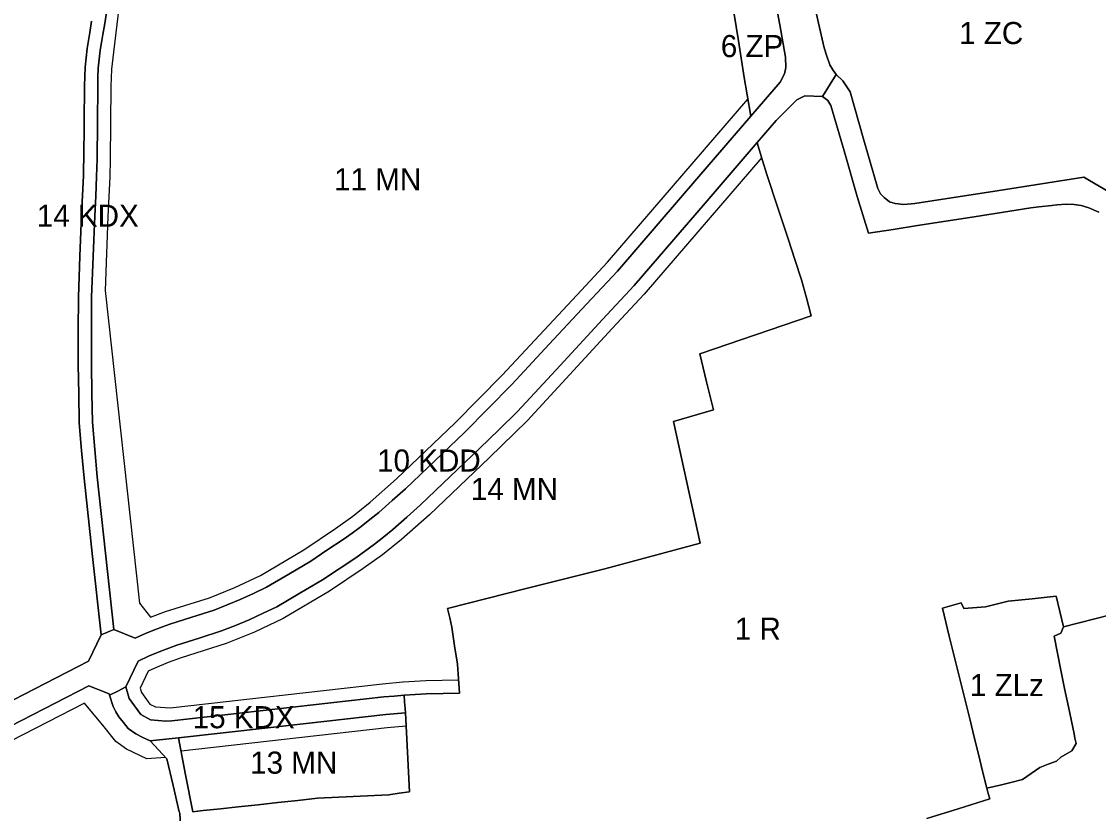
# Model space of a CAD drawing. Extents: x -294445 to -292055, y 21869 to 23693.
# Drawn here: x -293269.7 to -292783, y 22240.3 to 22598.3 of the extents above; entities that cross this region are included whole.
import ezdxf

# ---------------------------------------------------------------- set-up
doc = ezdxf.new("R2010")
doc.units = 0
for name, color, linetype in [('linie_rozgraniczajace', 7, 'Continuous'), ('linie_zabudowy_nieprzekraczalne', 7, 'Continuous'), ('oznaczenia_przeznaczen', 7, 'Continuous')]:
    doc.layers.add(name, color=color, linetype=linetype)

msp = doc.modelspace()

# ---------------------------------------------------------------- linework, layer by layer
at = {"layer": 'linie_rozgraniczajace'}
for points in [[(-293302.714, 22276.673), (-293239.368, 22309.206), (-293233.787, 22321.003), (-293227.916, 22323.482), (-293223.142, 22321.508), (-293218.368, 22319.534), (-293216.059, 22320.643), (-293212.623, 22322.071), (-293209.188, 22323.5), (-293205.936, 22324.686), (-293202.683, 22325.873), (-293192.683, 22329.039), (-293182.683, 22332.205), (-293176.773, 22334.589), (-293170.863, 22336.974), (-293164.904, 22339.78), (-293158.945, 22342.587), (-293148.961, 22348.488), (-293138.978, 22354.39), (-293131.669, 22359.27), (-293124.361, 22364.15), (-293120.317, 22367.055), (-293116.273, 22369.96), (-293112.279, 22373.19), (-293108.285, 22376.421), (-293102.214, 22381.775), (-293096.144, 22387.128), (-293082.827, 22399.85), (-293069.51, 22412.572), (-293058.845, 22423.426), (-293048.18, 22434.28), (-293031.26, 22452.385), (-293014.34, 22470.49), (-293007.373, 22478.002), (-293000.405, 22485.515), (-292963.658, 22528.21), (-292940.132, 22555.546), (-292926.911, 22570.906), (-292924.849, 22574.683), (-292924.231, 22577.549), (-292924.4, 22582.147), (-292927.04, 22596.744), (-292929.68, 22611.34)], [(-292948.75, 22608.3), (-292945.745, 22589.63), (-292943.07, 22572.98), (-292941.74, 22565.09), (-292940.132, 22555.546), (-292963.658, 22528.21), (-293000.405, 22485.515), (-293007.373, 22478.002), (-293014.34, 22470.49), (-293031.26, 22452.385), (-293048.18, 22434.28), (-293058.845, 22423.426), (-293069.51, 22412.572), (-293082.827, 22399.85), (-293096.144, 22387.128), (-293102.214, 22381.775), (-293108.285, 22376.421), (-293112.279, 22373.19), (-293116.273, 22369.96), (-293120.317, 22367.055), (-293124.361, 22364.15), (-293131.669, 22359.27), (-293138.978, 22354.39), (-293148.961, 22348.488), (-293158.945, 22342.587), (-293164.904, 22339.78), (-293170.863, 22336.974), (-293176.773, 22334.589), (-293182.683, 22332.205), (-293192.683, 22329.039), (-293202.683, 22325.873), (-293205.936, 22324.686), (-293209.188, 22323.5)], [(-292911.95, 22608.56), (-292909.465, 22597.52), (-292906.98, 22586.48), (-292905.695, 22582.565), (-292904.41, 22578.65), (-292902.992, 22576.501), (-292901.574, 22574.353), (-292907.675, 22564.371), (-292915.782, 22564.716), (-292919.3, 22562.86), (-292928.711, 22553.485), (-292937.25, 22543.564), (-292960.769, 22516.238), (-292992.826, 22478.991), (-293007.132, 22463.557), (-293026.336, 22442.779), (-293045.54, 22422), (-293054.052, 22413.69), (-293062.563, 22405.379), (-293075.972, 22392.57), (-293089.38, 22379.76)], [(-292768.799, 22515.737), (-292789.634, 22527.91), (-292827.817, 22521.943), (-292866.001, 22515.976), (-292871.033, 22515.575), (-292874.885, 22515.97), (-292877.503, 22516.81), (-292879.91, 22518.674), (-292881.568, 22520.42), (-292882.733, 22522.768), (-292886.349, 22535.383), (-292889, 22544.63), (-292895.267, 22566.493), (-292898.581, 22571.486), (-292901.574, 22574.353), (-292902.992, 22576.501), (-292904.41, 22578.65), (-292905.695, 22582.565), (-292906.98, 22586.48), (-292909.465, 22597.52), (-292911.95, 22608.56)], [(-293231.274, 22602.401), (-293232.126, 22597.42), (-293232.979, 22592.438), (-293233.538, 22588.876), (-293234.098, 22585.314), (-293234.558, 22581.267), (-293235.019, 22577.221), (-293235.151, 22573.148), (-293235.283, 22569.075), (-293235.433, 22552.559), (-293235.583, 22536.042), (-293235.666, 22532.166), (-293235.75, 22528.29), (-293236.185, 22519.39), (-293236.62, 22510.49), (-293237.325, 22492.06), (-293238.03, 22473.63), (-293238.09, 22458.43), (-293238.15, 22443.23), (-293237.885, 22430.2), (-293237.62, 22417.17), (-293236.555, 22404.835), (-293235.49, 22392.5), (-293231.703, 22357.991), (-293227.916, 22323.482), (-293233.787, 22321.003), (-293237.624, 22356.459), (-293241.462, 22391.915), (-293242.538, 22404.383), (-293243.615, 22416.851), (-293243.882, 22430.016), (-293244.15, 22443.181), (-293244.09, 22458.469), (-293244.03, 22473.757), (-293243.322, 22492.254), (-293242.614, 22510.751), (-293242.181, 22519.626), (-293241.747, 22528.501), (-293241.665, 22532.275), (-293241.584, 22536.049), (-293241.432, 22552.659), (-293241.28, 22569.27), (-293241.144, 22573.464), (-293241.008, 22577.658), (-293240.526, 22581.888), (-293240.045, 22586.119), (-293239.472, 22589.764), (-293238.9, 22593.41), (-293238.035, 22598.462)], [(-293238.15, 22443.23), (-293238.09, 22458.43), (-293238.03, 22473.63), (-293237.325, 22492.06), (-293236.62, 22510.49), (-293236.185, 22519.39), (-293235.75, 22528.29), (-293235.666, 22532.166), (-293235.583, 22536.042), (-293235.433, 22552.559), (-293235.283, 22569.075), (-293235.151, 22573.148), (-293235.019, 22577.221), (-293234.558, 22581.267), (-293234.098, 22585.314), (-293233.538, 22588.876), (-293232.979, 22592.438), (-293232.126, 22597.42), (-293231.274, 22602.401)], [(-293238.035, 22598.462), (-293238.9, 22593.41), (-293239.472, 22589.764), (-293240.045, 22586.119), (-293240.526, 22581.888), (-293241.008, 22577.658), (-293241.144, 22573.464), (-293241.28, 22569.27), (-293241.432, 22552.659), (-293241.584, 22536.049), (-293241.665, 22532.275), (-293241.747, 22528.501), (-293242.181, 22519.626), (-293242.614, 22510.751), (-293243.322, 22492.254), (-293244.03, 22473.757), (-293244.09, 22458.469), (-293244.15, 22443.181), (-293243.882, 22430.016), (-293243.615, 22416.851), (-293242.538, 22404.383), (-293241.462, 22391.915), (-293237.624, 22356.459), (-293233.787, 22321.003), (-293239.368, 22309.206), (-293302.714, 22276.673)], [(-292907.675, 22564.371), (-292901.574, 22574.353), (-292898.581, 22571.486), (-292895.267, 22566.493), (-292889, 22544.63), (-292886.349, 22535.383), (-292882.733, 22522.768), (-292881.568, 22520.42), (-292879.91, 22518.674), (-292877.503, 22516.81), (-292874.885, 22515.97), (-292871.033, 22515.575), (-292866.001, 22515.976), (-292827.817, 22521.943), (-292789.634, 22527.91), (-292768.799, 22515.737)], [(-293211.569, 22273.104), (-293198.792, 22274.534), (-293195.54, 22257.812), (-293192.288, 22241.091), (-293189.979, 22241.341), (-293187.67, 22241.59), (-293179.71, 22242.45), (-293171.75, 22243.31), (-293162.795, 22244.275), (-293153.84, 22245.24), (-293144.885, 22246.21), (-293135.93, 22247.18), (-293119.8, 22247.94), (-293103.67, 22248.7), (-293099, 22249.415), (-293094.33, 22250.13), (-293095.241, 22267.972), (-293096.153, 22285.815), (-293096.35, 22287.76), (-293096.583, 22290.774), (-293096.816, 22293.787), (-293086.802, 22294.362), (-293079.135, 22294.525), (-293071.707, 22294.683), (-293072.224, 22301.206), (-293072.74, 22307.73), (-293074.02, 22316.145), (-293075.3, 22324.56), (-293076.215, 22328.759), (-293077.129, 22332.958), (-293041.636, 22341.933), (-293006.142, 22350.907), (-292962.965, 22362.455), (-292975.055, 22417.55), (-292956.986, 22422.836), (-292960.106, 22435.435), (-292963.227, 22448.035), (-292938.004, 22456.662), (-292912.78, 22465.29), (-292914.995, 22473.4), (-292917.21, 22481.51), (-292920.25, 22490.755), (-292923.29, 22500), (-292928.085, 22514.575), (-292932.88, 22529.15), (-292934.82, 22535.535), (-292936.76, 22541.92), (-292937.25, 22543.564), (-292928.711, 22553.485), (-292919.3, 22562.86), (-292915.782, 22564.716), (-292907.675, 22564.371), (-292905.369, 22562.538), (-292903.896, 22560.408), (-292897.996, 22539.773), (-292892.095, 22519.138), (-292886.873, 22502.593), (-292875.852, 22504.315), (-292864.83, 22506.037), (-292839.175, 22510.046), (-292813.521, 22514.056), (-292809.957, 22514.486), (-292804.112, 22515.161), (-292801.831, 22515.405), (-292797.432, 22515.688), (-292794.006, 22515.602), (-292790.828, 22515.084), (-292787.374, 22514.014), (-292782.899, 22512.059)], [(-292782.899, 22512.059), (-292787.374, 22514.014), (-292790.828, 22515.084), (-292794.006, 22515.602), (-292797.432, 22515.688), (-292801.831, 22515.405), (-292804.112, 22515.161), (-292809.957, 22514.486), (-292813.521, 22514.056), (-292839.175, 22510.046), (-292864.83, 22506.037), (-292875.852, 22504.315), (-292886.873, 22502.593), (-292892.095, 22519.138), (-292897.996, 22539.773), (-292903.896, 22560.408), (-292905.369, 22562.538), (-292907.675, 22564.371)], [(-293209.188, 22323.5), (-293212.623, 22322.071), (-293216.059, 22320.643), (-293218.368, 22319.534), (-293223.142, 22321.508), (-293227.916, 22323.482), (-293231.703, 22357.991), (-293235.49, 22392.5), (-293236.555, 22404.835), (-293237.62, 22417.17), (-293237.885, 22430.2), (-293238.15, 22443.23)], [(-293089.38, 22379.76), (-293095.605, 22374.27), (-293101.886, 22368.732), (-293106.018, 22365.392), (-293110.207, 22362.005), (-293118.666, 22355.929), (-293126.159, 22350.925), (-293133.653, 22345.921), (-293143.956, 22339.831), (-293154.26, 22333.74), (-293160.559, 22330.773), (-293166.859, 22327.806), (-293173.078, 22325.297), (-293179.298, 22322.787), (-293189.378, 22319.596), (-293199.459, 22316.405), (-293205.553, 22314.181), (-293211.971, 22311.512), (-293216.93, 22309.131), (-293222.576, 22297.526), (-293226.245, 22295.638), (-293229.914, 22293.751), (-293230.084, 22294.316), (-293239.255, 22298.022), (-293300.311, 22266.665)], [(-292845.06, 22335.58), (-292853.54, 22333.17), (-292850.408, 22320.485), (-292847.275, 22307.8), (-292844.143, 22295.115), (-292841.01, 22282.43), (-292839.123, 22274.76), (-292837.235, 22267.09), (-292835.348, 22259.42), (-292833.46, 22251.75), (-292832.807, 22249.337), (-292832.154, 22246.923), (-292846.352, 22242.462), (-292860.55, 22238)], [(-292770.49, 22331.84), (-292784.655, 22328.23), (-292798.82, 22324.62), (-292802.17, 22338.51), (-292812.96, 22337.355), (-292823.75, 22336.2), (-292834.09, 22333.77), (-292843.88, 22332.96), (-292845.06, 22335.58)], [(-292860.55, 22238), (-292846.352, 22242.462), (-292832.154, 22246.923), (-292832.807, 22249.337), (-292833.46, 22251.75), (-292826.76, 22253.22), (-292822.08, 22254.46), (-292817.4, 22255.7), (-292813.425, 22258.4), (-292809.45, 22261.1), (-292805.725, 22262.55), (-292802, 22264), (-292800, 22265.78), (-292795, 22268.6), (-292793.15, 22271.96), (-292793.646, 22274.358), (-292794.052, 22276.316), (-292796.575, 22288.505), (-292798.288, 22296.778), (-292800, 22305.05), (-292801.5, 22312.75), (-292803, 22320.45), (-292800, 22321.81), (-292798.82, 22324.62), (-292784.655, 22328.23), (-292770.49, 22331.84)], [(-293300.311, 22266.665), (-293239.255, 22298.022), (-293230.084, 22294.316), (-293229.914, 22293.751), (-293228.358, 22288.586), (-293227.036, 22286.275), (-293225.714, 22283.964), (-293223.596, 22281.353), (-293221.478, 22278.743), (-293218.113, 22276.283), (-293214.841, 22274.694), (-293211.569, 22273.104), (-293203.98, 22264.94), (-293201.209, 22253.006), (-293198.438, 22241.072), (-293198.22, 22240.45), (-293197.93, 22234.635)], [(-293197.93, 22234.635), (-293198.22, 22240.45), (-293198.438, 22241.072), (-293201.209, 22253.006), (-293203.98, 22264.94), (-293211.569, 22273.104)]]:
    msp.add_lwpolyline(points, dxfattribs=at)
for points in [[(-292948.75, 22608.3), (-292929.68, 22611.34), (-292927.04, 22596.744), (-292924.4, 22582.147), (-292924.231, 22577.549), (-292924.849, 22574.683), (-292926.911, 22570.906), (-292940.132, 22555.546), (-292941.74, 22565.09), (-292943.07, 22572.98), (-292945.745, 22589.63)], [(-293222.576, 22297.526), (-293216.93, 22309.131), (-293211.971, 22311.512), (-293205.553, 22314.181), (-293199.459, 22316.405), (-293189.378, 22319.596), (-293179.298, 22322.787), (-293173.078, 22325.297), (-293166.859, 22327.806), (-293160.559, 22330.773), (-293154.26, 22333.74), (-293143.956, 22339.831), (-293133.653, 22345.921), (-293126.159, 22350.925), (-293118.666, 22355.929), (-293110.207, 22362.005), (-293106.018, 22365.392), (-293101.886, 22368.732), (-293095.605, 22374.27), (-293089.38, 22379.76), (-293075.972, 22392.57), (-293062.563, 22405.379), (-293054.052, 22413.69), (-293045.54, 22422), (-293026.336, 22442.779), (-293007.132, 22463.557), (-292992.826, 22478.991), (-292960.769, 22516.238), (-292937.25, 22543.564), (-292936.76, 22541.92), (-292934.82, 22535.535), (-292932.88, 22529.15), (-292928.085, 22514.575), (-292923.29, 22500), (-292920.25, 22490.755), (-292917.21, 22481.51), (-292914.995, 22473.4), (-292912.78, 22465.29), (-292938.004, 22456.662), (-292963.227, 22448.035), (-292960.106, 22435.435), (-292956.986, 22422.836), (-292975.055, 22417.55), (-292962.965, 22362.455), (-293006.142, 22350.907), (-293041.636, 22341.933), (-293077.129, 22332.958), (-293076.215, 22328.759), (-293075.3, 22324.56), (-293074.02, 22316.145), (-293072.74, 22307.73), (-293072.224, 22301.206), (-293071.707, 22294.683), (-293079.135, 22294.525), (-293086.802, 22294.362), (-293096.816, 22293.787), (-293101.372, 22293.381), (-293105.927, 22292.975), (-293153.88, 22287.54), (-293201.834, 22282.106), (-293204.5, 22281.96), (-293207.95, 22282.315), (-293211.4, 22282.67), (-293215.8, 22285.1), (-293221, 22292.26)], [(-292853.54, 22333.17), (-292845.06, 22335.58), (-292843.88, 22332.96), (-292834.09, 22333.77), (-292823.75, 22336.2), (-292812.96, 22337.355), (-292802.17, 22338.51), (-292798.82, 22324.62), (-292800, 22321.81), (-292803, 22320.45), (-292801.5, 22312.75), (-292800, 22305.05), (-292798.288, 22296.778), (-292796.575, 22288.505), (-292794.052, 22276.316), (-292793.646, 22274.358), (-292793.15, 22271.96), (-292795, 22268.6), (-292800, 22265.78), (-292802, 22264), (-292805.725, 22262.55), (-292809.45, 22261.1), (-292813.425, 22258.4), (-292817.4, 22255.7), (-292822.08, 22254.46), (-292826.76, 22253.22), (-292833.46, 22251.75), (-292835.348, 22259.42), (-292837.235, 22267.09), (-292839.123, 22274.76), (-292841.01, 22282.43), (-292844.143, 22295.115), (-292847.275, 22307.8), (-292850.408, 22320.485)], [(-293229.914, 22293.751), (-293226.245, 22295.638), (-293222.576, 22297.526), (-293221, 22292.26), (-293215.8, 22285.1), (-293211.4, 22282.67), (-293207.95, 22282.315), (-293204.5, 22281.96), (-293201.834, 22282.106), (-293153.88, 22287.54), (-293105.927, 22292.975), (-293101.372, 22293.381), (-293096.816, 22293.787), (-293096.583, 22290.774), (-293096.35, 22287.76), (-293096.153, 22285.815), (-293105.121, 22285.015), (-293158.345, 22279.06), (-293198.792, 22274.534), (-293211.569, 22273.104), (-293214.841, 22274.694), (-293218.113, 22276.283), (-293221.478, 22278.743), (-293223.596, 22281.353), (-293225.714, 22283.964), (-293227.036, 22286.275), (-293228.358, 22288.586)], [(-293198.792, 22274.534), (-293158.345, 22279.06), (-293105.121, 22285.015), (-293096.153, 22285.815), (-293095.241, 22267.972), (-293094.33, 22250.13), (-293099, 22249.415), (-293103.67, 22248.7), (-293119.8, 22247.94), (-293135.93, 22247.18), (-293144.885, 22246.21), (-293153.84, 22245.24), (-293162.795, 22244.275), (-293171.75, 22243.31), (-293179.71, 22242.45), (-293187.67, 22241.59), (-293189.979, 22241.341), (-293192.288, 22241.091), (-293195.54, 22257.812)]]:
    msp.add_lwpolyline(points, close=True, dxfattribs=at)
at = {"layer": 'linie_zabudowy_nieprzekraczalne'}
for points in [[(-293225.657, 22604.489), (-293228.151, 22584.509), (-293229.03, 22576.783), (-293229.284, 22568.951), (-293229.583, 22535.95), (-293229.753, 22528.079), (-293230.626, 22510.229), (-293231.908, 22476.706), (-293216.462, 22335.306), (-293211.369, 22329.091), (-293204.618, 22331.554), (-293184.714, 22337.855), (-293173.266, 22342.474), (-293161.756, 22347.895), (-293142.173, 22359.471), (-293127.778, 22369.083), (-293119.913, 22374.733), (-293112.157, 22381.006), (-293100.202, 22391.549), (-293073.724, 22416.845), (-293052.512, 22438.432), (-293018.731, 22474.578), (-293004.88, 22489.513), (-292941.428, 22563.237)], [(-292935.192, 22536.758), (-292988.35, 22474.993), (-293002.728, 22459.482), (-293041.238, 22417.815), (-293058.395, 22401.063), (-293085.322, 22375.339), (-293097.957, 22364.195), (-293106.567, 22357.232), (-293115.249, 22350.996), (-293130.458, 22340.84), (-293151.449, 22328.432), (-293164.456, 22322.306), (-293177.267, 22317.137), (-293197.524, 22310.724), (-293203.371, 22308.59), (-293209.519, 22306.034), (-293212.448, 22304.627), (-293216.157, 22297.005), (-293215.545, 22294.959), (-293211.73, 22289.707), (-293209.185, 22288.517), (-293202.51, 22288.067), (-293106.531, 22298.945), (-293097.334, 22299.765), (-293097.176, 22299.777), (-293087.037, 22300.359), (-293072.182, 22300.674)], [(-293204.609, 22265.617), (-293213.115, 22264.961), (-293222.254, 22269.401), (-293227.037, 22272.897), (-293232.336, 22279.428), (-293232.336, 22279.428), (-293232.336, 22279.428), (-293241.307, 22290.223), (-293358.47, 22230.051)], [(-293095.846, 22279.818), (-293104.517, 22279.045), (-293197.618, 22268.494)]]:
    msp.add_lwpolyline(points, dxfattribs=at)

# ---------------------------------------------------------------- texts
at = {"layer": 'oznaczenia_przeznaczen'}
for s, p in [('1 ZC', (-292845.98, 22588.095)), ('6 ZP', (-292953.679, 22582.197)), ('11 MN', (-293128.446, 22521.988)), ('14 KDX', (-293262.799, 22505.49)), ('10 KDD', (-293109.006, 22394.85)), ('14 MN', (-293066.647, 22381.941)), ('1 R', (-292947.351, 22318.824)), ('1 ZLz', (-292841.108, 22293.345)), ('15 KDX', (-293192.356, 22278.824)), ('13 MN', (-293166.385, 22258.272))]:
    msp.add_text(s, height=10, dxfattribs=at).set_placement(p)

doc.saveas('drawing.dxf')
